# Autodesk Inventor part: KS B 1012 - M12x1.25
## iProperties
Created: 2009-02
Part Number: KS B 1012 - M12x1.25
Material: 강, 연강
Description: 6각 너트
Document SubType Name: Modeling
Standard: KS B 1012
Designer: KYOUNG IL JANG
Standards Organization: KS
Language: ko-KR
Size Designation: M12x1.25
Categories: <MemberInstance><Categories><Category DisplayName="조임쇠" InternalName="e4da775c-781d-43d5-af7c-5136215cf5a6" Mnemonic="FSTN"><Category DisplayName="너트" InternalN
Density: 1 g/cm^3
IsCustomPart: 0
Author: KYOUNG IL JANG
